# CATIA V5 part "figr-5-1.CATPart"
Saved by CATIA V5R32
Part number: Part1
Bounding box of the stored display mesh (mm): x -23 to 23, y -104 to 104, z 0 to 68
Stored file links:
  D:\PROJECTS\Project 2022\CATIA V5 6R 2022\Resources\Part Files\c05_catia_v5_6r2022_prt\figr-5-1.CATPart
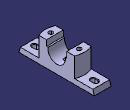
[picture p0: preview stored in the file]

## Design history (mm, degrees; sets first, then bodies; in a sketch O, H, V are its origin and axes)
Sketch1 on yz-plane, origin (0, 0, 0), H (0, 1, 0), V (0, 0, 1)
  line L1 (0, 0) -> (104, 0)
  point P1 (104, 0)
  line L2 (104, 0) -> (100, 14)
  point P2 (100, 14)
  line L3 (100, 14) -> (54, 14)
  point P3 (54, 14)
  line L4 (54, 14) -> (54, 68)
  point P4 (54, 68)
  line L5 (54, 68) -> (28, 68)
  point P5 (28, 68)
  line L6 (28, 68) -> (28, 52)
  point P6 (28, 52)
  line L7 (28, 52) -> (23.6643, 52)
  axis line L8 (0, 0) -> (0, 150)
  point P8 (0, 0)
  construction line L9 through (0, 0) direction (-1, 0)
  construction line L10 through (0, 0) direction (0, 1)
  point P13 (-104, 0)
  point P14 (-100, 14)
  point P15 (-54, 14)
  point P16 (-54, 68)
  point P17 (-28, 68)
  point P18 (-28, 52)
  line L11 (0, 0) -> (-104, 0)
  line L12 (-104, 0) -> (-100, 14)
  line L13 (-100, 14) -> (-54, 14)
  line L14 (-54, 14) -> (-54, 68)
  line L15 (-54, 68) -> (-28, 68)
  line L16 (-28, 68) -> (-28, 52)
  line L17 (-28, 52) -> (-23.6643, 52)
  arc A1 centre (0, 48) radius 24 from (-23.6643, 52) to (23.6643, 52) ccw
  point P19 (0, 48)
  point P20 (13.2665, 68)
  distance P1 P13 = 208
  length L2 V = 14
  length L2 H = 4
  distance L4 L14 = 108
  distance L16 L6 = 56
  distance L1 L5 = 68
  length L6 = 16
  distance P19 L7 = 4
  radius A1 = 24
  horizontal: L1 H, L3 H, L5 H, L7 H
  vertical: L4 V, L6 V, L8 V
  symmetry: O P8 L8, H L9 L8, V L10 L8, P1 P13 L8, P2 P14 L8, P3 P15 L8, P4 P16 L8, P5 P17 L8, P6 P18 L8, L1 L11 L8, L2 L12 L8, L3 L13 L8, L4 L14 L8, L5 L15 L8, L6 L16 L8, L7 L17 L8
  coincidence: P19 L8, A1 P20, P20 L5, O P8
Pad1: profile Sketch1, direction (1, 0, 0), length 23, mirrored extent
Body1 (main body)
  Sketch2 on face of Pad1, origin (0, 0, 68), H (1, 0, 0), V (0, 1, 0)
    arc A1 centre (0, 0) radius 54 from (-23, 48.8569) to (23, 48.8569) cw
    point P1 (0, 0)
    point P2 (-23, 48.8569)
    point P3 (23, 48.8569)
    reference projected line E1 (23, 54) -> (23, 28) from edge [face of Pad1 | face of Pad1]
    reference projected line E2 (-23, 54) -> (-23, 28) from edge [face of Pad1 | face of Pad1]
    reference projected line E3 (-23, 54) -> (23, 54) from edge [face of Pad1 | face of Pad1]
    axis line L1 (-38.3733, 0) -> (57.2772, 0)
    point P4 (-38.3733, 0)
    point P6 (-23, -48.8569)
    point P7 (23, -48.8569)
    arc A2 centre (0, 0) radius 54 from (-23, -48.8569) to (23, -48.8569) ccw
    line L2 (-23, 48.8569) -> (-23, -48.8569)
    point P9 (-23, -48.8569)
    line L3 (23, 48.8569) -> (23, -48.8569)
    coincidence: P3 E1, P2 E2, P1 O, P4 H, P9 P6
    tangency: A1 E3
    horizontal: L1 H
    symmetry: P2 P6 L1, P3 P7 L1, A1 A2 L1
    vertical: L2 V, L3 V
  Pocket1: profile Sketch2, direction (0, 0, -1), up to face of Pad1, outer side
  Sketch3 on face of Pad1, origin (0, 0, 0), H (1, 0, 0), V (0, -1, 0)
    line L1 (-13, 52) -> (13, 52)
    line L2 (13, 52) -> (13, 26)
    line L3 (13, 26) -> (-13, 26)
    line L4 (-13, 26) -> (-13, 52)
    axis line L5 (13, 26) -> (-13, 52)
    point P5 (0, 39)
    length L2 = 26
    length L1 = 26
    distance P5 O H = 0
    distance P5 H = 39
    horizontal: L1 H, L3 H
    vertical: L2 V, L4 V
    midpoint: P5 L5
  Pocket2: profile Sketch3, direction (0, 0, 1), length 10
  Sketch4 on face of Pocket2, origin (0, -39, 10), H (1, 0, 0), V (0, -1, 0)
    point P1 (0, 0)
    reference projected point E1 (0, 0) from vertex of Sketch7
    coincidence: E1 P1
  Hole1: placed by Sketch4, at (0, -39, 10) direction (0, 0, 1), diameter 12, through (limit type 3)
  Sketch5 on face of Pad1, origin (0, 0, 14), H (1, 0, 0), V (0, 1, 0)
    construction line L1 (0, -85) -> (0, -77)
    point P1 (0, -85)
    line L2 (-6, -85) -> (-6, -77)
    line L3 (6, -77) -> (6, -85)
    arc A1 centre (0, -77) radius 6 from (-6, -77) to (6, -77) cw
    arc A2 centre (0, -85) radius 6 from (6, -85) to (-6, -85) cw
    point P7 (0, -81)
    distance A1 A2 = 20
    distance L3 L2 = 12
    distance P7 H = 81
    coincidence: P1 V
    vertical: L1 V
    tangency: A1 L2, A2 L2, A1 L3, A2 L3
    parallelism: L1 L2
    midpoint: P7 L1
  Pocket3: profile Sketch5, direction (0, 0, -1), through (limit type 3)
  Chamfer1: length 1.5, angle 45, on 1 edge
  Sketch6 on yz-plane, origin (0, 0, 0), H (0, 1, 0), V (0, 0, 1)
    axis line L1 (0, 0) -> (0, 35.393)
    reference projected arc E1 centre (0, 48) radius 24 from (-23.6643, 52) to (23.6643, 52) ccw from edge [face of Pad1 | face of Pad1]
    projected arc E2 centre (0, 48) radius 24 from (0, 24) to (4, 24.3357) ccw from edge [face of Pad1 | face of Pad1]
    point P4 (4, 24.3357)
    line L2 (4, 24.3357) -> (4, 16)
    line L3 (4, 16) -> (0, 16)
    point P6 (0, 16)
    line L4 (0, 16) -> (0, 24)
    point P7 (0, 24)
    point P8 (0, 24)
    radius about axis L2 L1 = 4
    distance E1 L3 = 8
    vertical: L1 V, L2 V, L4 V
    coincidence: P4 E1, P6 L1, P7 E1, L1 P8, P7 P8
    horizontal: L3 H
  Groove1: profile Sketch6, axis Sketch6.L1, angle 360
  Mirror1: of Pocket2, Sketch3, Hole1, Pocket3, Sketch5, Chamfer1, about zx-plane
  Sketch7 on face of Pocket2, origin (0, 0, 10), H (1, 0, 0), V (0, -1, 0)
    point P1 (0, 39)
    axis line L1 (13, 26) -> (-13, 52)
    point P2 (13, 26)
    point P3 (-13, 52)
    reference projected point E1 (13, 26) from vertex [face of Pocket2 | face of Pad1 | face of Pocket2]
    reference projected point E2 (-13, 52) from vertex [face of Pocket2 | face of Pad1 | face of Pocket2]
    coincidence: P1 V, L1 P1, E1 P2, P3 E2
    midpoint: P1 L1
